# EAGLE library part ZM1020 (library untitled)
ZM1020: medium numeric topview nixie tube
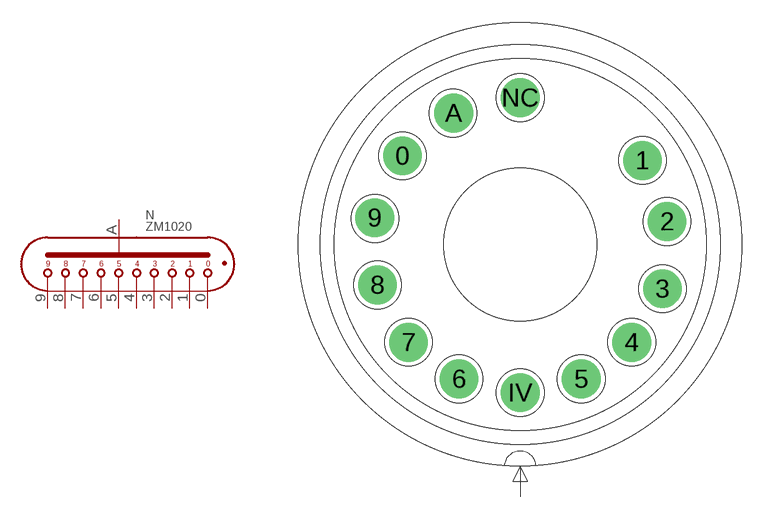
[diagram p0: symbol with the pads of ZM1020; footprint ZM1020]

Designator prefix N

## ZM1020  [ZM1020]
0  0  pas
1  1  pas
2  2  pas
3  3  pas
4  4  pas
5  5  pas
6  6  pas
7  7  pas
8  8  pas
9  9  pas
A  A  pas

## Footprint ZM1020 (pad centres in mm)
Socket B13B print
drill 1.422 pad 2.54 round: 0 -7.7,5.8; 1 8,5.5; 2 9.6,1.5; 3 9.3,-2.9; 4 7.3,-6.4; 5 4,-8.8; 6 -4,-8.8; 7 -7.3,-6.4; 8 -9.327,-2.646; 9 -9.5,1.75; A -4.35,8.6; IV 0,-9.7; NC 0,9.6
